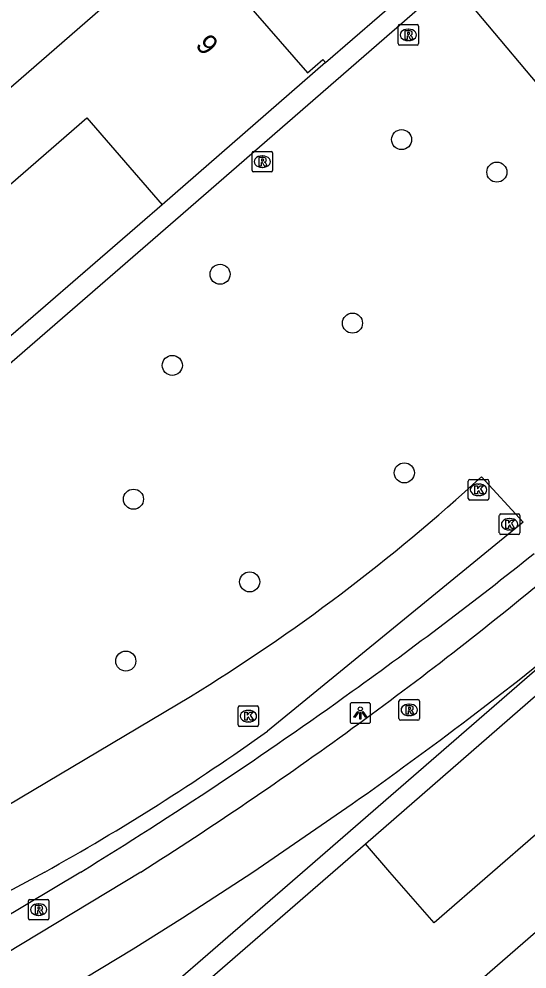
# Model space of a CAD drawing. Extents: x 155888 to 156864, y 383882 to 384671.
# Drawn here: x 156447.75 to 156472.51, y 384245.27 to 384291.57 of the extents above; entities that cross this region are included whole.
import ezdxf

# ---------------------------------------------------------------- set-up
doc = ezdxf.new("R2010")
doc.units = 0
for name, color, linetype in [('IMGEO_Boom', 7, 'Continuous'), ('IMGEO_Fietspad_gesloten', 7, 'Continuous'), ('IMGEO_Greppel_droge_sloot', 7, 'Continuous'), ('IMGEO_Groenvoorziening', 7, 'Continuous'), ('IMGEO_Haag', 7, 'Continuous'), ('IMGEO_Kolk', 7, 'Continuous'), ('IMGEO_Lichtpunt', 7, 'Continuous'), ('IMGEO_Muur', 7, 'Continuous'), ('IMGEO_Pand', 7, 'Continuous'), ('IMGEO_Pand_nummerreeks', 7, 'Continuous'), ('IMGEO_Rioolput', 7, 'Continuous'), ('IMGEO_Voetpad_open', 7, 'Continuous')]:
    doc.layers.add(name, color=color, linetype=linetype)

msp = doc.modelspace()

# ---------------------------------------------------------------- linework, layer by layer
at = {"layer": 'IMGEO_Boom'}
for centre in [(156466.396, 384285.695), (156471.042, 384284.11), (156457.546, 384279.133), (156464.001, 384276.75), (156455.219, 384274.692), (156466.529, 384269.452), (156453.324, 384268.17), (156458.99, 384264.142), (156452.953, 384260.281)]:
    msp.add_circle(centre, 0.489, dxfattribs=at)
at = {"layer": 'IMGEO_Fietspad_gesloten'}
for points in [[(156443.421, 384240.556), (156447.852, 384243.001), (156450.974, 384244.837), (156453.305, 384246.256), (156455.714, 384247.767), (156459.141, 384249.997), (156463.992, 384253.323)], [(156453.681, 384250), (156446.236, 384245.512), (156442.084, 384243.292)]]:
    msp.add_lwpolyline(points, dxfattribs=at)
for centre, radius, start, end in [((156349.485, 384414.569), 194.778, 306.00684, 309.61614), ((156343.728, 384423.44), 208.335, 305.25848, 309.13506), ((156350.175, 384413.468), 193.482, 302.34134, 306.0332)]:
    msp.add_arc(centre, radius, start, end, dxfattribs=at)
at = {"layer": 'IMGEO_Greppel_droge_sloot'}
for points in [[(156470.285, 384269.26), (156472.33, 384267.049), (156459.859, 384256.869)], [(156448.999, 384250), (156445.802, 384248.288), (156444.75, 384250), (156443.932, 384251.329), (156456.104, 384258.555)]]:
    msp.add_lwpolyline(points, dxfattribs=at)
for centre, radius, start, end in [((156407.734, 384337.377), 92.48, 301.536, 312.56109), ((156393.43, 384349.875), 114.293, 299.09094, 305.53614)]:
    msp.add_arc(centre, radius, start, end, dxfattribs=at)
at = {"layer": 'IMGEO_Groenvoorziening'}
msp.add_lwpolyline([(156473.684, 384287.624), (156469.998, 384291.998)], dxfattribs=at)
at = {"layer": 'IMGEO_Haag'}
for points in [[(156468.8, 384293.389), (156467.285, 384292.117), (156455.381, 384281.767), (156445.564, 384273.279), (156432.408, 384261.791)], [(156462.691, 384289.448), (156466.642, 384292.883)], [(156454.727, 384282.523), (156444.906, 384274.032)], [(156464.634, 384251.373), (156474.433, 384259.907)]]:
    msp.add_lwpolyline(points, dxfattribs=at)
at = {"layer": 'IMGEO_Kolk'}
for p, q in [((156469.647, 384268.202), (156469.647, 384269.054)), ((156469.722, 384269.128), (156470.574, 384269.128)), ((156470.135, 384268.908), (156470.16, 384268.908)), ((156470.648, 384269.054), (156470.648, 384268.202)), ((156470.158, 384268.348), (156470.133, 384268.348)), ((156470.574, 384268.128), (156469.722, 384268.128)), ((156471.161, 384266.524), (156471.161, 384267.376)), ((156471.236, 384267.45), (156472.088, 384267.45)), ((156472.162, 384267.376), (156472.162, 384266.524)), ((156471.649, 384267.23), (156471.674, 384267.23)), ((156472.088, 384266.45), (156471.236, 384266.45)), ((156471.672, 384266.67), (156471.647, 384266.67)), ((156458.427, 384257.171), (156458.427, 384258.023)), ((156458.502, 384258.097), (156459.354, 384258.097)), ((156458.915, 384257.877), (156458.94, 384257.877)), ((156459.428, 384258.023), (156459.428, 384257.171)), ((156458.938, 384257.317), (156458.913, 384257.317)), ((156459.354, 384257.097), (156458.502, 384257.097))]:
    msp.add_line(p, q, dxfattribs=at)
for points in [[(156469.647, 384268.202), (156469.647, 384269.054)], [(156469.722, 384269.128), (156470.574, 384269.128)], [(156469.968, 384268.828), (156470.091, 384268.828), (156470.091, 384268.677), (156470.221, 384268.828), (156470.385, 384268.828), (156470.239, 384268.677), (156470.392, 384268.428), (156470.24, 384268.428), (156470.155, 384268.592), (156470.091, 384268.525), (156470.091, 384268.428), (156469.968, 384268.428), (156469.968, 384268.828)], [(156470.648, 384269.054), (156470.648, 384268.202)], [(156470.574, 384268.128), (156469.722, 384268.128)], [(156471.161, 384266.524), (156471.161, 384267.376)], [(156471.236, 384267.45), (156472.088, 384267.45)], [(156472.162, 384267.376), (156472.162, 384266.524)], [(156471.482, 384267.15), (156471.605, 384267.15), (156471.605, 384266.999), (156471.735, 384267.15), (156471.899, 384267.15), (156471.753, 384266.999), (156471.906, 384266.75), (156471.754, 384266.75), (156471.669, 384266.914), (156471.605, 384266.847), (156471.605, 384266.75), (156471.482, 384266.75), (156471.482, 384267.15)], [(156472.088, 384266.45), (156471.236, 384266.45)], [(156458.427, 384257.171), (156458.427, 384258.023)], [(156458.502, 384258.097), (156459.354, 384258.097)], [(156458.748, 384257.797), (156458.871, 384257.797), (156458.871, 384257.646), (156459.001, 384257.797), (156459.165, 384257.797), (156459.019, 384257.646), (156459.172, 384257.397), (156459.02, 384257.397), (156458.935, 384257.561), (156458.871, 384257.494), (156458.871, 384257.397), (156458.748, 384257.397), (156458.748, 384257.797)], [(156459.428, 384258.023), (156459.428, 384257.171)], [(156459.354, 384257.097), (156458.502, 384257.097)]]:
    msp.add_lwpolyline(points, dxfattribs=at)
for centre, start, end in [((156469.724, 384269.052), 91.552, 178.448), ((156469.724, 384269.052), 91.552, 178.448), ((156470.572, 384269.052), 1.552, 88.448), ((156470.572, 384269.052), 1.552, 88.448), ((156469.724, 384268.204), 181.552, 268.448), ((156469.724, 384268.204), 181.552, 268.448), ((156470.572, 384268.204), 271.552, 358.448), ((156470.572, 384268.204), 271.552, 358.448), ((156471.238, 384267.374), 91.552, 178.448), ((156471.238, 384267.374), 91.552, 178.448), ((156472.086, 384267.374), 1.552, 88.448), ((156472.086, 384267.374), 1.552, 88.448), ((156471.238, 384266.526), 181.552, 268.448), ((156471.238, 384266.526), 181.552, 268.448), ((156472.086, 384266.526), 271.552, 358.448), ((156472.086, 384266.526), 271.552, 358.448), ((156458.504, 384258.021), 91.552, 178.448), ((156458.504, 384258.021), 91.552, 178.448), ((156459.352, 384258.021), 1.552, 88.448), ((156459.352, 384258.021), 1.552, 88.448), ((156458.504, 384257.173), 181.552, 268.448), ((156458.504, 384257.173), 181.552, 268.448), ((156459.352, 384257.173), 271.552, 358.448), ((156459.352, 384257.173), 271.552, 358.448)]:
    msp.add_arc(centre, 0.0765, start, end, dxfattribs=at)
for centre, major_axis, ratio, start_param, end_param in [((156470.134, 384268.628), (-0.387, 0.002), 0.722429, 4.712389, 7.853982), ((156470.159, 384268.628), (-0.39, 0.002), 0.717154, 1.570796, 4.712389), ((156471.648, 384266.95), (-0.387, 0.002), 0.722429, 4.712389, 7.853982), ((156471.673, 384266.95), (-0.39, 0.002), 0.717154, 1.570796, 4.712389), ((156458.914, 384257.597), (-0.387, 0.002), 0.722429, 4.712389, 7.853982), ((156458.939, 384257.597), (-0.39, 0.002), 0.717154, 1.570796, 4.712389)]:
    msp.add_ellipse(centre, major_axis=major_axis, ratio=ratio, start_param=start_param, end_param=end_param, dxfattribs=at)
at = {"layer": 'IMGEO_Lichtpunt'}
for p, q in [((156463.886, 384258.153), (156463.886, 384257.346)), ((156463.886, 384258.153), (156463.886, 384257.346)), ((156464.788, 384258.248), (156463.98, 384258.248)), ((156464.788, 384258.248), (156463.98, 384258.248)), ((156464.882, 384257.346), (156464.882, 384258.153)), ((156464.882, 384257.346), (156464.882, 384258.153)), ((156463.98, 384257.252), (156464.788, 384257.252)), ((156463.98, 384257.252), (156464.788, 384257.252))]:
    msp.add_line(p, q, dxfattribs=at)
for points in [[(156464.26, 384257.817), (156464.299, 384257.789), (156464.111, 384257.527), (156464.073, 384257.554), (156464.26, 384257.817)], [(156464.362, 384257.769), (156464.409, 384257.769), (156464.409, 384257.447), (156464.362, 384257.447), (156464.362, 384257.769)], [(156464.472, 384257.789), (156464.51, 384257.816), (156464.697, 384257.554), (156464.658, 384257.526), (156464.472, 384257.789)]]:
    msp.add_lwpolyline(points, dxfattribs=at)
msp.add_circle((156464.385, 384257.951), 0.0994, dxfattribs=at)
for centre, start, end in [((156463.98, 384258.153), 90, 180), ((156463.98, 384258.153), 90, 180), ((156464.788, 384258.153), 0, 90), ((156464.788, 384258.153), 0, 90), ((156463.98, 384257.346), 180, 270), ((156463.98, 384257.346), 180, 270), ((156464.788, 384257.346), 270, 0), ((156464.788, 384257.346), 270, 360)]:
    msp.add_arc(centre, 0.0946, start, end, dxfattribs=at)
at = {"layer": 'IMGEO_Muur'}
msp.add_lwpolyline([(156464.634, 384251.373), (156474.433, 384259.907)], dxfattribs=at)
at = {"layer": 'IMGEO_Pand'}
for points in [[(156443.861, 384285.236), (156456.677, 384296.374)], [(156456.677, 384296.374), (156456.793, 384296.241), (156456.038, 384295.584), (156461.803, 384288.953), (156462.554, 384289.606), (156462.691, 384289.448)], [(156462.691, 384289.448), (156454.727, 384282.523)], [(156446.199, 384282.547), (156451.045, 384286.758), (156454.727, 384282.523)], [(156472.925, 384251.817), (156470.832, 384250), (156467.977, 384247.522), (156465.826, 384250), (156464.634, 384251.373)], [(156456.692, 384244.48), (156463.052, 384250), (156464.634, 384251.373)], [(156462.393, 384237.92), (156475.277, 384249.109)]]:
    msp.add_lwpolyline(points, dxfattribs=at)
at = {"layer": 'IMGEO_Rioolput'}
for p, q in [((156466.223, 384290.372), (156466.223, 384291.224)), ((156466.298, 384291.298), (156467.15, 384291.298)), ((156466.711, 384291.078), (156466.736, 384291.078)), ((156467.224, 384291.224), (156467.224, 384290.372)), ((156466.734, 384290.518), (156466.709, 384290.518)), ((156467.15, 384290.298), (156466.298, 384290.298)), ((156459.107, 384284.195), (156459.107, 384285.047)), ((156459.182, 384285.121), (156460.034, 384285.121)), ((156460.108, 384285.047), (156460.108, 384284.195)), ((156459.595, 384284.901), (156459.62, 384284.901)), ((156460.034, 384284.121), (156459.182, 384284.121)), ((156459.618, 384284.341), (156459.593, 384284.341)), ((156466.268, 384257.476), (156466.268, 384258.328)), ((156466.343, 384258.402), (156467.195, 384258.402)), ((156466.756, 384258.182), (156466.781, 384258.182)), ((156467.269, 384258.328), (156467.269, 384257.476)), ((156467.195, 384257.402), (156466.343, 384257.402)), ((156466.779, 384257.622), (156466.754, 384257.622)), ((156448.203, 384247.743), (156448.203, 384248.595)), ((156448.278, 384248.669), (156449.13, 384248.669)), ((156448.691, 384248.449), (156448.716, 384248.449)), ((156449.204, 384248.595), (156449.204, 384247.743)), ((156449.13, 384247.669), (156448.278, 384247.669)), ((156448.714, 384247.889), (156448.689, 384247.889))]:
    msp.add_line(p, q, dxfattribs=at)
for points in [[(156466.223, 384290.372), (156466.223, 384291.224)], [(156466.298, 384291.298), (156467.15, 384291.298)], [(156466.812, 384290.996), (156466.56, 384290.998), (156466.56, 384290.598)], [(156467.224, 384291.224), (156467.224, 384290.372)], [(156466.56, 384290.598), (156466.684, 384290.598), (156466.684, 384290.76), (156466.695, 384290.76)], [(156466.738, 384290.917), (156466.684, 384290.917), (156466.684, 384290.836)], [(156466.684, 384290.836), (156466.736, 384290.836)], [(156466.742, 384290.731), (156466.813, 384290.598), (156466.953, 384290.598), (156466.888, 384290.724)], [(156467.15, 384290.298), (156466.298, 384290.298)], [(156459.107, 384284.195), (156459.107, 384285.047)], [(156459.182, 384285.121), (156460.034, 384285.121)], [(156460.108, 384285.047), (156460.108, 384284.195)], [(156459.696, 384284.819), (156459.444, 384284.821), (156459.444, 384284.421)], [(156459.444, 384284.421), (156459.568, 384284.421), (156459.568, 384284.583), (156459.579, 384284.583)], [(156459.622, 384284.74), (156459.568, 384284.74), (156459.568, 384284.659)], [(156459.568, 384284.659), (156459.62, 384284.659)], [(156459.626, 384284.554), (156459.697, 384284.421), (156459.837, 384284.421), (156459.772, 384284.547)], [(156460.034, 384284.121), (156459.182, 384284.121)], [(156466.268, 384257.476), (156466.268, 384258.328)], [(156466.343, 384258.402), (156467.195, 384258.402)], [(156467.269, 384258.328), (156467.269, 384257.476)], [(156466.857, 384258.1), (156466.605, 384258.102), (156466.605, 384257.702)], [(156466.605, 384257.702), (156466.729, 384257.702), (156466.729, 384257.864), (156466.74, 384257.864)], [(156466.783, 384258.021), (156466.729, 384258.021), (156466.729, 384257.94)], [(156466.729, 384257.94), (156466.781, 384257.94)], [(156466.787, 384257.835), (156466.858, 384257.702), (156466.998, 384257.702), (156466.933, 384257.828)], [(156467.195, 384257.402), (156466.343, 384257.402)], [(156448.203, 384247.743), (156448.203, 384248.595)], [(156448.278, 384248.669), (156449.13, 384248.669)], [(156449.204, 384248.595), (156449.204, 384247.743)], [(156448.792, 384248.367), (156448.54, 384248.369), (156448.54, 384247.969)], [(156448.54, 384247.969), (156448.664, 384247.969), (156448.664, 384248.131), (156448.675, 384248.131)], [(156448.718, 384248.288), (156448.664, 384248.288), (156448.664, 384248.207)], [(156448.664, 384248.207), (156448.716, 384248.207)], [(156448.722, 384248.102), (156448.793, 384247.969), (156448.933, 384247.969), (156448.868, 384248.095)], [(156449.13, 384247.669), (156448.278, 384247.669)]]:
    msp.add_lwpolyline(points, dxfattribs=at)
for centre, radius, start, end in [((156466.3, 384291.222), 0.0765, 91.552, 178.448), ((156466.3, 384291.222), 0.0765, 91.552, 178.448), ((156466.811, 384290.886), 0.109, 350.3612, 89.416), ((156467.148, 384291.222), 0.0765, 1.552, 88.448), ((156467.148, 384291.222), 0.0765, 1.552, 88.448), ((156466.694, 384290.707), 0.0533, 26.0293, 88.6989), ((156466.72, 384291.025), 0.19, 274.7715, 282.9687), ((156466.744, 384290.821), 0.0964, 77.0061, 93.1865), ((156466.758, 384290.878), 0.0378, 276.6634, 79.6772), ((156466.809, 384290.886), 0.112, 277.5842, 350.9817), ((156466.793, 384290.671), 0.108, 29.5134, 73.7905), ((156466.3, 384290.374), 0.0765, 181.552, 268.448), ((156466.3, 384290.374), 0.0765, 181.552, 268.448), ((156467.148, 384290.374), 0.0765, 271.552, 358.448), ((156467.148, 384290.374), 0.0765, 271.552, 358.448), ((156459.184, 384285.045), 0.0765, 91.552, 178.448), ((156459.184, 384285.045), 0.0765, 91.552, 178.448), ((156460.032, 384285.045), 0.0765, 1.552, 88.448), ((156460.032, 384285.045), 0.0765, 1.552, 88.448), ((156459.578, 384284.53), 0.0533, 26.0293, 88.6989), ((156459.604, 384284.848), 0.19, 274.7715, 282.9687), ((156459.628, 384284.644), 0.0964, 77.0061, 93.1865), ((156459.642, 384284.701), 0.0378, 276.6634, 79.6772), ((156459.695, 384284.709), 0.109, 350.3612, 89.416), ((156459.693, 384284.709), 0.112, 277.5842, 350.9817), ((156459.677, 384284.494), 0.108, 29.5134, 73.7905), ((156459.184, 384284.197), 0.0765, 181.552, 268.448), ((156459.184, 384284.197), 0.0765, 181.552, 268.448), ((156460.032, 384284.197), 0.0765, 271.552, 358.448), ((156460.032, 384284.197), 0.0765, 271.552, 358.448), ((156466.345, 384258.326), 0.0765, 91.552, 178.448), ((156466.345, 384258.326), 0.0765, 91.552, 178.448), ((156467.193, 384258.326), 0.0765, 1.552, 88.448), ((156467.193, 384258.326), 0.0765, 1.552, 88.448), ((156466.739, 384257.811), 0.0533, 26.0293, 88.6989), ((156466.765, 384258.129), 0.19, 274.7715, 282.9687), ((156466.789, 384257.925), 0.0964, 77.0061, 93.1865), ((156466.803, 384257.982), 0.0378, 276.6634, 79.6772), ((156466.856, 384257.99), 0.109, 350.3612, 89.416), ((156466.854, 384257.99), 0.112, 277.5842, 350.9817), ((156466.838, 384257.775), 0.108, 29.5134, 73.7905), ((156466.345, 384257.478), 0.0765, 181.552, 268.448), ((156466.345, 384257.478), 0.0765, 181.552, 268.448), ((156467.193, 384257.478), 0.0765, 271.552, 358.448), ((156467.193, 384257.478), 0.0765, 271.552, 358.448), ((156448.28, 384248.593), 0.0765, 91.552, 178.448), ((156448.28, 384248.593), 0.0765, 91.552, 178.448), ((156449.128, 384248.593), 0.0765, 1.552, 88.448), ((156449.128, 384248.593), 0.0765, 1.552, 88.448), ((156448.674, 384248.078), 0.0533, 26.0293, 88.6989), ((156448.7, 384248.396), 0.19, 274.7715, 282.9687), ((156448.724, 384248.192), 0.0964, 77.0061, 93.1865), ((156448.738, 384248.249), 0.0378, 276.6634, 79.6772), ((156448.791, 384248.257), 0.109, 350.3612, 89.416), ((156448.789, 384248.257), 0.112, 277.5842, 350.9817), ((156448.773, 384248.042), 0.108, 29.5134, 73.7905), ((156448.28, 384247.745), 0.0765, 181.552, 268.448), ((156448.28, 384247.745), 0.0765, 181.552, 268.448), ((156449.128, 384247.745), 0.0765, 271.552, 358.448), ((156449.128, 384247.745), 0.0765, 271.552, 358.448)]:
    msp.add_arc(centre, radius, start, end, dxfattribs=at)
for centre, major_axis, ratio, start_param, end_param in [((156466.71, 384290.798), (-0.387, 0.002), 0.722429, 4.712389, 7.853982), ((156466.735, 384290.798), (-0.39, 0.002), 0.717154, 1.570796, 4.712389), ((156459.594, 384284.621), (-0.387, 0.002), 0.722429, 4.712389, 7.853982), ((156459.619, 384284.621), (-0.39, 0.002), 0.717154, 1.570796, 4.712389), ((156466.755, 384257.902), (-0.387, 0.002), 0.722429, 4.712389, 7.853982), ((156466.78, 384257.902), (-0.39, 0.002), 0.717154, 1.570796, 4.712389), ((156448.69, 384248.169), (-0.387, 0.002), 0.722429, 4.712389, 7.853982), ((156448.715, 384248.169), (-0.39, 0.002), 0.717154, 1.570796, 4.712389)]:
    msp.add_ellipse(centre, major_axis=major_axis, ratio=ratio, start_param=start_param, end_param=end_param, dxfattribs=at)
at = {"layer": 'IMGEO_Voetpad_open'}
for points in [[(156451.452, 384239.846), (156450.764, 384240.642), (156461.558, 384250), (156475.218, 384261.843)], [(156450.761, 384250), (156445.42, 384246.815)]]:
    msp.add_lwpolyline(points, dxfattribs=at)
for centre, radius, start, end in [((156334.171, 384439.404), 222.414, 305.7104, 308.57725), ((156334.281, 384439.292), 222.259, 301.60584, 305.70432)]:
    msp.add_arc(centre, radius, start, end, dxfattribs=at)

# ---------------------------------------------------------------- texts
at = {"layer": 'IMGEO_Pand_nummerreeks'}
msp.add_text('9', height=1, rotation=311.002, dxfattribs=at).set_placement((156456.302, 384290.281))

doc.saveas('drawing.dxf')
